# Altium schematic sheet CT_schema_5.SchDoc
size 258 x 142 mm
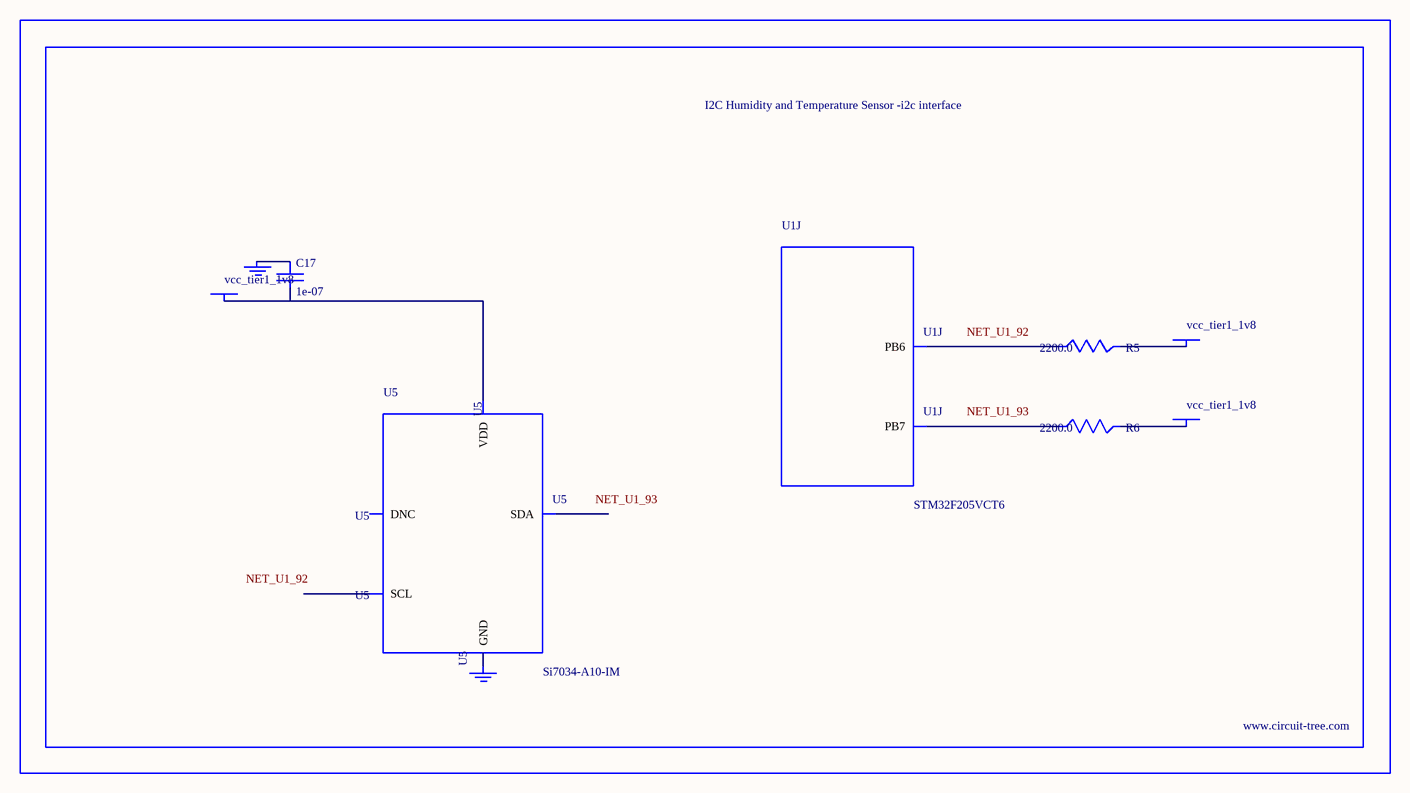
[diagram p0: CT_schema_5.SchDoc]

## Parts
BORDER4  (no value)
C17  1e-07  [C0402]
GND_INSTANCE_4_0  (no value)
GND_INSTANCE_4_1  (no value)
POWER_INSTANCE_4_0  vcc_tier1_1v8
POWER_INSTANCE_4_1  vcc_tier1_1v8
POWER_INSTANCE_4_2  vcc_tier1_1v8
R5  2200.0  [R0603]
R6  2200.0  [R0603]
U1  STM32F205VCT6  [LQFP100]  (part J of 10)
U5  Si7034-A10-IM  [SI7034-A10-IM]

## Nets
NetC17_1: C17.1 GND_INSTANCE_4_0.0(GND)
NetC17_2: C17.2 POWER_INSTANCE_4_0.0(PWR) U5.1(VDD)
NetGND_INSTANCE_4_1_0: GND_INSTANCE_4_1.0(GND) U5.5(GND)
NetPOWER_INSTANCE_4_1_0: POWER_INSTANCE_4_1.0(PWR) R5.2
NetPOWER_INSTANCE_4_2_0: POWER_INSTANCE_4_2.0(PWR) R6.2
NetR5_1: R5.1 U1.92(PB6)
NetR6_1: R6.1 U1.93(PB7)

Not connected (* = marked no-connect by the designer): U5 2(SCL) 3(DNC) 4(SDA)

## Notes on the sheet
- Labels drawn without touching a wire or pin: NET_U1_92, NET_U1_93

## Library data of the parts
BORDER4 = BORDER_PAGE4
C17 = C0402C104K3RACTU
GND_INSTANCE_4_0 GND_INSTANCE_4_1 = GND
POWER_INSTANCE_4_0-POWER_INSTANCE_4_2 = PWR
R5 R6 = RC0603JR-072K2L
